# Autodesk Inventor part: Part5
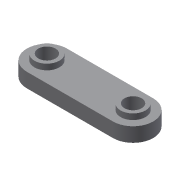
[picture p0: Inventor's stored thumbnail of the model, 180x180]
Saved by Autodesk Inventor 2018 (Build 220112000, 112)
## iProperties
Shininess: 77.0
Length Units: 11269
Angle Units: 11279
Time Units: 11290
Mass Units: 11283
Length Display Precision: 3
Angle Display Precision: 2
Created: 2002-01
Part Number: Part5
Document SubType Name: Modeling
Designer: ***
Density: 1 g/cm^3
Material: Generic
Appearance: Default
Density: 0.0
Volumn: 0.0
Area: 0.0
PropertySet Name: Model Information
Control State: 0
Master: False
Checked Out: False
Author: ***
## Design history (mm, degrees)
sketch "Sketch1"
  geometry: L1 (-33.118, 12.346)-(26.882, 12.361); L2 (-33.111, -15.654)-(26.889, -15.639); C1 r 6 at (-33.114, -1.654); C2 r 6 at (26.886, -1.639); A1 r 14 centre (-33.114, -1.654) between (-33.118, 12.346) and (-33.111, -15.654); A2 r 14 centre (26.886, -1.639) between (26.889, -15.639) and (26.882, 12.361)
  constraints: 4 centre point, 4 end point, 4 point on circle, 4 tangent, 2 coincident, 2 equal radius
  dimensions: "d0" = 60 distance of L1.start L1.end; "d1" = 14 radius of A1; "d2" = 12 diameter of C1
extrude "Extrusion1" new body sketch "Sketch1" distance "d3" = 10; taper "d4" = 0 deg
sketch "Sketch2"
  geometry: C1 r 6 at (26.886, -1.639) reference; C2 r 6 at (-33.114, -1.654) reference; C3 r 8.694 at (-33.114, -1.654); C4 r 8.694 at (26.886, -1.639)
  constraints: 2 centre point, 2 coincident, 1 equal radius
extrude "Extrusion2" join sketch "Sketch2" distance "d5" = 4; taper "d6" = 0 deg
body "Solid1"
